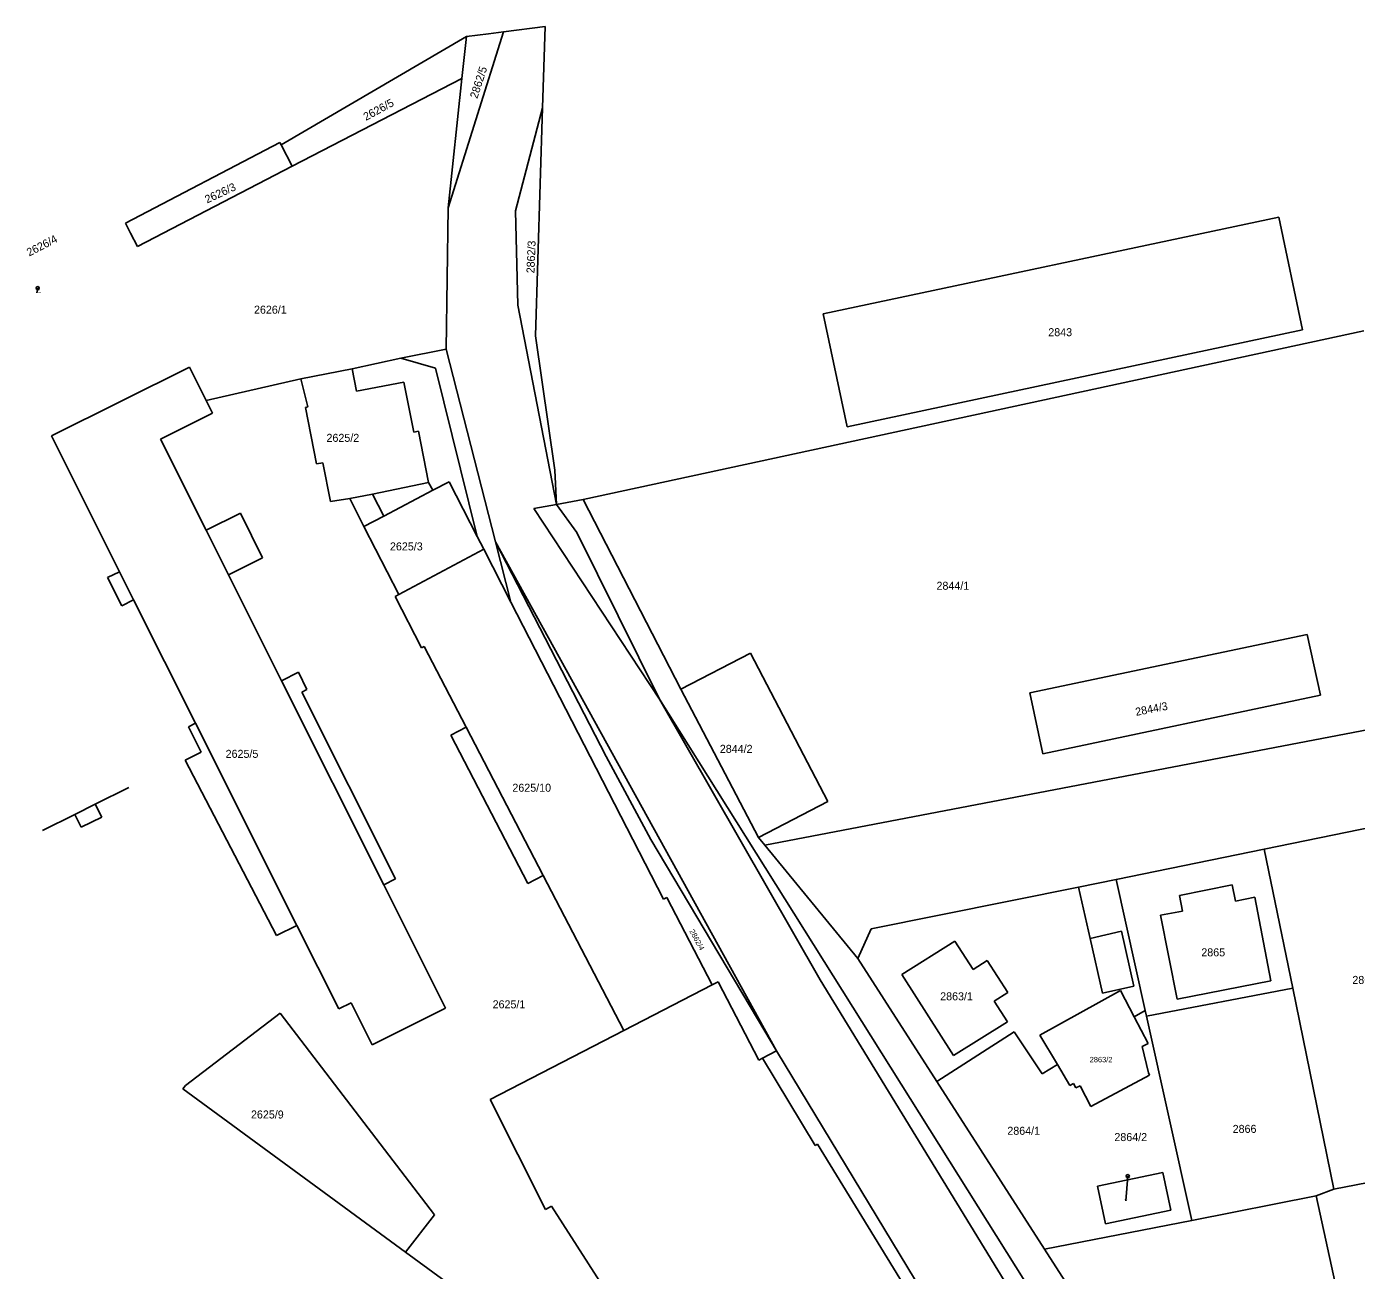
# Model space of a CAD drawing. Extents: x -722132 to -721608, y -1046877 to -1046449.
# Drawn here: x -722130.2 to -721988.9, y -1046586.7 to -1046454.6 of the extents above; entities that cross this region are included whole.
import ezdxf

# ---------------------------------------------------------------- set-up
doc = ezdxf.new("R2010")
doc.units = 0
for name, color, linetype in [('Vrstva 1', 7, 'Continuous'), ('Vrstva 16', 7, 'Continuous'), ('Vrstva 18', 7, 'Continuous'), ('Vrstva 19', 7, 'Continuous'), ('Vrstva 4', 7, 'Continuous'), ('Vrstva 6', 7, 'Continuous')]:
    doc.layers.add(name, color=color, linetype=linetype)

msp = doc.modelspace()

# ---------------------------------------------------------------- linework, layer by layer
at = {"layer": 'Vrstva 1'}
for points in [[(-722079.52, -1046455.14), (-722075.08, -1046454.58)], [(-722075.36, -1046463.21), (-722075.08, -1046454.58)], [(-722103.12, -1046467.14), (-722083.45, -1046455.63)], [(-722083.93, -1046460.09), (-722083.45, -1046455.63)], [(-722083.45, -1046455.63), (-722081.09, -1046455.34)], [(-722081.09, -1046455.34), (-722079.52, -1046455.14)], [(-722101.95, -1046469.41), (-722083.93, -1046460.09)], [(-722085.39, -1046473.84), (-722083.93, -1046460.09)], [(-722078.23, -1046474.14), (-722075.36, -1046463.21)], [(-722076.12, -1046487.43), (-722075.36, -1046463.21)], [(-722119.66, -1046475.46), (-722103.25, -1046466.89)], [(-722103.25, -1046466.89), (-722103.12, -1046467.14)], [(-722103.12, -1046467.14), (-722101.95, -1046469.41)], [(-722118.39, -1046477.92), (-722101.95, -1046469.41)], [(-722085.61, -1046488.85), (-722085.39, -1046473.84)], [(-722078.23, -1046474.14), (-722077.99, -1046484.15)], [(-722119.66, -1046475.46), (-722119.12, -1046476.51)], [(-722045.57, -1046485.08), (-721997.19, -1046474.82)], [(-721997.19, -1046474.82), (-721994.65, -1046486.8)], [(-722119.12, -1046476.51), (-722118.39, -1046477.92)], [(-722077.99, -1046484.15), (-722073.89, -1046505.33)], [(-722045.57, -1046485.08), (-722043.03, -1046497.1)], [(-722071.04, -1046504.79), (-721988.16, -1046486.9)], [(-722043.03, -1046497.1), (-721994.65, -1046486.8)], [(-722076.12, -1046487.43), (-722074.05, -1046501.69)], [(-722095.58, -1046490.92), (-722090.43, -1046489.79)], [(-722090.43, -1046489.79), (-722085.61, -1046488.85)], [(-722085.61, -1046488.85), (-722080.37, -1046509.3)], [(-722127.53, -1046498.05), (-722112.85, -1046490.75)], [(-722112.85, -1046490.75), (-722111.09, -1046494.28)], [(-722101.03, -1046492), (-722095.58, -1046490.92)], [(-722111.09, -1046494.28), (-722101.03, -1046492)], [(-722101.03, -1046492), (-722100.3, -1046494.97)], [(-722115.93, -1046498.38), (-722110.42, -1046495.62)], [(-722111.09, -1046494.28), (-722110.42, -1046495.62)], [(-722100.54, -1046495.02), (-722100.3, -1046494.97)], [(-722100.54, -1046495.02), (-722099.37, -1046501.03)], [(-722127.53, -1046498.05), (-722120.3, -1046512.47)], [(-722115.93, -1046498.38), (-722111.09, -1046508.06)], [(-722099.37, -1046501.03), (-722098.71, -1046500.9)], [(-722098.71, -1046500.9), (-722097.9, -1046505.03)], [(-722074.05, -1046501.69), (-722073.89, -1046505.33)], [(-722093.42, -1046504.25), (-722087.49, -1046503.01)], [(-722087.49, -1046503.01), (-722087.01, -1046503.81)], [(-722087.01, -1046503.81), (-722085.28, -1046502.92)], [(-722085.28, -1046502.92), (-722082.32, -1046508.74)], [(-722097.9, -1046505.03), (-722095.83, -1046504.68)], [(-722095.83, -1046504.68), (-722093.42, -1046504.25)], [(-722095.83, -1046504.68), (-722094.35, -1046507.66)], [(-722073.89, -1046505.33), (-722071.04, -1046504.79)], [(-722071.04, -1046504.79), (-722060.68, -1046524.94)], [(-722111.09, -1046508.06), (-722107.45, -1046506.24)], [(-722107.45, -1046506.24), (-722105.09, -1046511)], [(-722094.35, -1046507.66), (-722090.63, -1046514.91)], [(-722082.32, -1046508.74), (-722081.6, -1046510.09)], [(-722080.37, -1046509.3), (-722078.73, -1046515.69)], [(-722080.37, -1046509.3), (-722050.51, -1046563.35)], [(-722108.71, -1046512.81), (-722105.09, -1046511)], [(-722090.63, -1046514.91), (-722081.6, -1046510.09)], [(-722081.6, -1046510.09), (-722078.73, -1046515.69)], [(-722121.55, -1046513.1), (-722120.3, -1046512.47)], [(-722121.55, -1046513.1), (-722120.05, -1046516.09)], [(-722108.71, -1046512.81), (-722103.08, -1046524.05)], [(-722091.02, -1046515.12), (-722090.63, -1046514.91)], [(-722091.02, -1046515.12), (-722088.21, -1046520.56)], [(-722120.05, -1046516.09), (-722118.8, -1046515.46)], [(-722118.8, -1046515.46), (-722112.22, -1046528.57)], [(-722078.73, -1046515.69), (-722062.53, -1046547.26)], [(-722023.62, -1046525.33), (-721994.17, -1046519.13)], [(-721994.17, -1046519.13), (-721992.77, -1046525.6)], [(-722088.21, -1046520.56), (-722087.94, -1046520.42)], [(-722087.94, -1046520.42), (-722083.49, -1046528.98)], [(-722060.68, -1046524.94), (-722053.3, -1046521.14)], [(-722053.3, -1046521.14), (-722045.08, -1046536.87)], [(-722103.08, -1046524.05), (-722101.3, -1046523.15)], [(-722101.3, -1046523.15), (-722100.38, -1046524.98)], [(-722100.92, -1046525.25), (-722100.38, -1046524.98)], [(-722100.92, -1046525.25), (-722090.98, -1046545.09)], [(-722060.68, -1046524.94), (-722052.43, -1046540.71)], [(-722023.62, -1046525.33), (-722022.24, -1046531.81)], [(-722051.77, -1046541.52), (-721967.65, -1046525.4)], [(-722022.24, -1046531.81), (-721992.77, -1046525.6)], [(-722112.97, -1046528.95), (-722112.22, -1046528.57)], [(-722112.97, -1046528.95), (-722111.63, -1046531.63)], [(-722085.12, -1046529.83), (-722083.49, -1046528.98)], [(-722085.12, -1046529.83), (-722076.93, -1046545.59)], [(-722113.33, -1046532.48), (-722111.63, -1046531.63)], [(-722113.33, -1046532.48), (-722103.61, -1046551.12)], [(-722122.86, -1046537.16), (-722119.29, -1046535.4)], [(-722122.86, -1046537.16), (-722122.17, -1046538.55)], [(-722052.43, -1046540.71), (-722045.08, -1046536.87)], [(-722128.48, -1046539.94), (-722125.04, -1046538.24)], [(-722125.04, -1046538.24), (-722124.37, -1046539.61)], [(-722124.37, -1046539.61), (-722122.17, -1046538.55)], [(-721998.72, -1046541.93), (-721982.68, -1046538.64)], [(-722052.43, -1046540.71), (-722051.77, -1046541.52)], [(-722051.77, -1046541.52), (-722041.88, -1046553.56)], [(-722014.45, -1046545.17), (-721998.72, -1046541.93)], [(-721998.72, -1046541.93), (-721995.69, -1046556.7)], [(-722092.23, -1046545.72), (-722090.98, -1046545.09)], [(-722076.93, -1046545.59), (-722075.29, -1046544.73)], [(-722075.29, -1046544.73), (-722066.72, -1046561.21)], [(-722092.23, -1046545.72), (-722085.67, -1046558.83)], [(-722040.47, -1046550.4), (-722018.46, -1046545.98)], [(-722018.46, -1046545.98), (-722014.45, -1046545.17)], [(-722014.45, -1046545.17), (-722011.36, -1046559.09)], [(-722062.53, -1046547.26), (-722062.17, -1046547.07)], [(-722062.17, -1046547.07), (-722057.37, -1046556.35)], [(-722103.61, -1046551.12), (-722101.45, -1046550.03)], [(-722101.45, -1046550.03), (-722096.99, -1046558.91)], [(-722041.88, -1046553.56), (-722040.47, -1046550.4)], [(-722041.88, -1046553.56), (-722033.5, -1046566.61)], [(-722066.72, -1046561.21), (-722057.37, -1046556.35)], [(-722057.37, -1046556.35), (-722056.73, -1046556.02)], [(-722056.73, -1046556.02), (-722052.41, -1046564.34)], [(-722022.55, -1046561.7), (-722013.99, -1046556.96)], [(-722013.99, -1046556.96), (-722012.53, -1046559.75)], [(-722011.23, -1046559.68), (-721995.69, -1046556.7)], [(-721995.69, -1046556.7), (-721991.32, -1046578.06)], [(-722096.99, -1046558.91), (-722095.69, -1046558.26)], [(-722095.69, -1046558.26), (-722093.47, -1046562.72)], [(-722093.47, -1046562.72), (-722085.67, -1046558.83)], [(-722011.36, -1046559.09), (-722012.53, -1046559.75)], [(-722011.36, -1046559.09), (-722011.23, -1046559.68)], [(-722113.3, -1046567.03), (-722103.23, -1046559.36)], [(-722103.23, -1046559.36), (-722086.84, -1046580.78)], [(-722012.53, -1046559.75), (-722011.07, -1046562.56)], [(-722011.23, -1046559.68), (-722006.42, -1046581.36)], [(-722080.93, -1046568.53), (-722066.72, -1046561.21)], [(-722033.5, -1046566.61), (-722025.28, -1046561.35)], [(-722025.28, -1046561.35), (-722022.31, -1046565.8)], [(-722020.68, -1046564.82), (-722022.55, -1046561.7)], [(-722052.02, -1046564.13), (-722050.51, -1046563.35)], [(-722011.07, -1046562.56), (-722011.69, -1046562.88)], [(-722011.03, -1046565.71), (-722011.69, -1046562.88)], [(-722052.41, -1046564.34), (-722052.02, -1046564.13)], [(-722052.02, -1046564.13), (-722046.43, -1046573.42)], [(-722022.31, -1046565.8), (-722020.68, -1046564.82)], [(-722020.68, -1046564.82), (-722019.36, -1046567.03)], [(-722017.13, -1046569.26), (-722010.91, -1046565.93)], [(-722010.91, -1046565.93), (-722011.03, -1046565.71)], [(-722113.57, -1046567.39), (-722113.3, -1046567.03)], [(-722113.57, -1046567.39), (-722089.92, -1046584.74)], [(-722033.5, -1046566.61), (-722022.07, -1046584.43)], [(-722019.36, -1046567.03), (-722018.99, -1046566.82)], [(-722018.99, -1046566.82), (-722018.73, -1046567.29)], [(-722018.73, -1046567.29), (-722018.29, -1046567.09)], [(-722018.29, -1046567.09), (-722017.13, -1046569.26)], [(-722080.93, -1046568.53), (-722075.06, -1046580.19)], [(-722046.43, -1046573.42), (-722046.17, -1046573.26)], [(-722046.17, -1046573.26), (-722034.73, -1046591.91)], [(-721991.32, -1046578.06), (-721977.1, -1046575.28)], [(-722016.44, -1046577.73), (-722009.49, -1046576.26)], [(-722009.49, -1046576.26), (-722008.65, -1046580.27)], [(-722015.59, -1046581.74), (-722016.44, -1046577.73)], [(-722006.42, -1046581.36), (-721993.21, -1046578.75)], [(-721993.21, -1046578.75), (-721991.32, -1046578.06)], [(-721993.21, -1046578.75), (-721988.59, -1046600.03)], [(-722075.06, -1046580.19), (-722074.42, -1046579.87)], [(-722074.42, -1046579.87), (-722050.83, -1046616.6)], [(-722008.65, -1046580.27), (-722015.59, -1046581.74)], [(-722089.92, -1046584.74), (-722086.84, -1046580.78)], [(-722022.07, -1046584.43), (-722006.42, -1046581.36)], [(-722022.07, -1046584.43), (-722008.84, -1046605.03)], [(-722089.92, -1046584.74), (-722084.64, -1046588.61)]]:
    msp.add_lwpolyline(points, dxfattribs=at)
at = {"layer": 'Vrstva 16'}
for points in [[(-722129.08, -1046482.86), (-722128.98, -1046482.36)], [(-722013.43, -1046579.28), (-722013.22, -1046576.68)]]:
    msp.add_lwpolyline(points, dxfattribs=at)
for centre in [(-722128.98, -1046482.36), (-722013.22, -1046576.68)]:
    msp.add_circle(centre, 0.175, dxfattribs=at)
at = {"layer": 'Vrstva 4'}
for p, q in [((-722031.57, -1046551.7), (-722037.22, -1046555.26)), ((-722037.22, -1046555.26), (-722031.71, -1046563.86)), ((-722031.71, -1046563.86), (-722026, -1046560.29))]:
    msp.add_line(p, q, dxfattribs=at)
for points in [[(-722090.43, -1046489.79), (-722086.72, -1046490.87)], [(-722095.58, -1046490.92), (-722095.11, -1046493.31)], [(-722086.72, -1046490.87), (-722082.32, -1046508.74)], [(-722095.11, -1046493.31), (-722090.08, -1046492.33)], [(-722090.08, -1046492.33), (-722089.05, -1046497.64)], [(-722089.05, -1046497.64), (-722088.55, -1046497.55)], [(-722088.55, -1046497.55), (-722087.49, -1046503.01)], [(-722092.21, -1046506.57), (-722087.01, -1046503.81)], [(-722093.42, -1046504.25), (-722092.21, -1046506.57)], [(-722073.89, -1046505.33), (-722071.73, -1046508.3)], [(-722094.35, -1046507.66), (-722092.21, -1046506.57)], [(-722111.09, -1046508.06), (-722108.71, -1046512.81)], [(-722071.73, -1046508.3), (-722062.93, -1046526)], [(-722080.37, -1046509.3), (-722068.62, -1046532.11)], [(-722120.3, -1046512.47), (-722118.8, -1046515.46)], [(-722103.08, -1046524.05), (-722092.23, -1046545.72)], [(-722062.93, -1046526), (-722045.87, -1046555.83)], [(-722112.22, -1046528.57), (-722101.45, -1046550.03)], [(-722083.49, -1046528.98), (-722075.29, -1046544.73)], [(-722068.62, -1046532.11), (-722063.85, -1046540.91)], [(-722125.04, -1046538.24), (-722122.86, -1046537.16)], [(-722063.85, -1046540.91), (-722052.55, -1046559.94)], [(-722018.46, -1046545.98), (-722017.22, -1046551.42)], [(-722007.73, -1046546.85), (-722002.14, -1046545.73)], [(-722002.14, -1046545.73), (-722001.78, -1046547.46)], [(-722007.73, -1046546.85), (-722007.41, -1046548.52)], [(-722001.78, -1046547.46), (-721999.71, -1046547.03)], [(-721999.71, -1046547.03), (-721998.03, -1046555.91)], [(-722009.74, -1046548.96), (-722007.41, -1046548.52)], [(-722009.74, -1046548.96), (-722007.98, -1046557.87)], [(-722017.22, -1046551.42), (-722013.89, -1046550.66)], [(-722013.89, -1046550.66), (-722012.58, -1046556.48)], [(-722031.57, -1046551.7), (-722029.64, -1046554.73)], [(-722017.22, -1046551.42), (-722015.9, -1046557.24)], [(-722029.64, -1046554.73), (-722028.14, -1046553.78)], [(-722028.14, -1046553.78), (-722025.97, -1046557.16)], [(-722045.87, -1046555.83), (-722006.7, -1046619.85)], [(-722007.98, -1046557.87), (-721998.03, -1046555.91)], [(-722027.42, -1046558.08), (-722025.97, -1046557.16)], [(-722015.9, -1046557.24), (-722012.58, -1046556.48)], [(-722027.42, -1046558.08), (-722026, -1046560.29)], [(-722052.55, -1046559.94), (-722050.51, -1046563.35)], [(-722050.51, -1046563.35), (-722015.29, -1046621.57)]]:
    msp.add_lwpolyline(points, dxfattribs=at)
at = {"layer": 'Vrstva 6'}
for points in [[(-722085.39, -1046473.84), (-722079.52, -1046455.14)], [(-722076.28, -1046505.77), (-722073.89, -1046505.33)], [(-722076.28, -1046505.77), (-722062.93, -1046526)], [(-722062.93, -1046526), (-722023.01, -1046589.63)]]:
    msp.add_lwpolyline(points, dxfattribs=at)

# ---------------------------------------------------------------- texts
at = {"layer": 'Vrstva 16'}
msp.add_text('2626/4', height=0.85, rotation=27.4066, dxfattribs=at).set_placement((-722129.88, -1046479.01))
msp.add_text('2864/2', height=0.85, dxfattribs=at).set_placement((-722014.64, -1046572.94))
at = {"layer": 'Vrstva 18'}
for s, height, rotation, p in [('2862/5', 0.85, 72.0194, (-722082.3, -1046462.29)), ('2626/5', 0.85, 28.5922, (-722094.11, -1046464.6)), ('2626/3', 0.85, 24.9697, (-722110.99, -1046473.37)), ('2862/3', 0.85, 87.755, (-722076.23, -1046480.8)), ('2862/4', 0.57, 298.4777, (-722059.79, -1046550.64))]:
    msp.add_text(s, height=height, rotation=rotation, dxfattribs=at).set_placement(p)
for s, height, p in [('2626/4', 0.1, (-722129.08, -1046482.86)), ('2626/1', 0.85, (-722106.01, -1046485.07)), ('2844/1', 0.85, (-722033.53, -1046514.39)), ('2867/1', 0.85, (-721989.37, -1046556.25)), ('2864/1', 0.85, (-722026.01, -1046572.27)), ('2866', 0.85, (-722002.08, -1046572.07))]:
    msp.add_text(s, height=height, dxfattribs=at).set_placement(p)
at = {"layer": 'Vrstva 19'}
for s, height, p in [('2843', 0.85, (-722021.66, -1046487.46)), ('2625/2', 0.85, (-722098.31, -1046498.68)), ('2625/3', 0.85, (-722091.57, -1046510.21)), ('2844/2', 0.85, (-722056.54, -1046531.71)), ('2625/5', 0.85, (-722109.02, -1046532.24)), ('2625/10', 0.85, (-722078.57, -1046535.84)), ('2865', 0.85, (-722005.41, -1046553.32)), ('2863/1', 0.85, (-722033.14, -1046557.99)), ('2625/1', 0.85, (-722080.67, -1046558.84)), ('2863/2', 0.57, (-722017.26, -1046564.57)), ('2625/9', 0.85, (-722106.33, -1046570.54)), ('2864/2', 0.1, (-722013.64, -1046579.28))]:
    msp.add_text(s, height=height, dxfattribs=at).set_placement(p)
msp.add_text('2844/3', height=0.85, rotation=11.0393, dxfattribs=at).set_placement((-722012.33, -1046527.79))

doc.saveas('drawing.dxf')
